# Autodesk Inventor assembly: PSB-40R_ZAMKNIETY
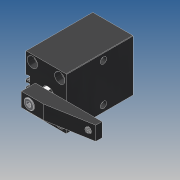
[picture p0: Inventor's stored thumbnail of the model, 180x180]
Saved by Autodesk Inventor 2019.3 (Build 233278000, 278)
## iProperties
Company: Î¢ÈíÖÐ¹ú
Created: 2013-10
Part Number: PSB-40R_ZAMKNIETY
Material: Ogólny
Description: STEP AP203
Document SubType Name: Assembly
Designer: CADENGINEERING4
Sending System: SolidWorks 2012
Preprocessor: SwSTEP 2.0
Title: PSB-40.STEP
Author: Î¢ÈíÓÃ»§
Revision Number: ÈÎºÎ
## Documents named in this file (6)
- E:\SERWER_ZAPAS\Pneumatic\PSB PNEUMATIC SWING\PSB-40\PSB-40R_ZAMKNIETY.iam
- E:\SERWER_ZAPAS\Pneumatic\PSB PNEUMATIC SWING\PSB-40\PSB40BT.ipt
- E:\SERWER_ZAPAS\Pneumatic\PSB PNEUMATIC SWING\PSB-40\PSB40HSG.ipt
- E:\SERWER_ZAPAS\Pneumatic\PSB PNEUMATIC SWING\PSB-40\PSB40YB.ipt
- E:\SERWER_ZAPAS\Pneumatic\PSB PNEUMATIC SWING\PSB-40\PSB40HG.ipt
- E:\SERWER_ZAPAS\Pneumatic\PSB PNEUMATIC SWING\PSB-40\socket head cap screw_iso_ISO 4762 M8 x 25 --- 25S.ipt
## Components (5 placed, 5 different names)
1. PSB40BT_1 — Zestawiające:1, Kątowe:1
2. PSB40HSG_2 — Zestawiające:1, Zestawiające:2, Zestawiające:3, Zestawiające:4
3. PSB40YB_3 — Zestawiające:3, Zestawiające:4, Zestawiające:5, Zestawiające:6, Kątowe:1
4. PSB40HG_4 — Zestawiające:2
5. socket head cap screw_iso_ISO 4762 M8 x 25 --- 25S_5 — Zestawiające:5, Zestawiające:6
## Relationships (7: Mate 6, Angle 1)
- Zestawiające:1 [Mate]: PSB40BT_1 ↔ PSB40HSG_2
- Zestawiające:2 [Mate]: PSB40HSG_2 ↔ PSB40HG_4
- Zestawiające:3 [Mate]: PSB40HSG_2 ↔ PSB40YB_3
- Zestawiające:4 [Mate]: PSB40HSG_2 ↔ PSB40YB_3
- Zestawiające:5 [Mate]: PSB40YB_3 ↔ socket head cap screw_iso_ISO 4762 M8 x 25 --- 25S_5
- Zestawiające:6 [Mate]: PSB40YB_3 ↔ socket head cap screw_iso_ISO 4762 M8 x 25 --- 25S_5
- Kątowe:1 [Angle]: PSB40BT_1 ↔ PSB40YB_3
